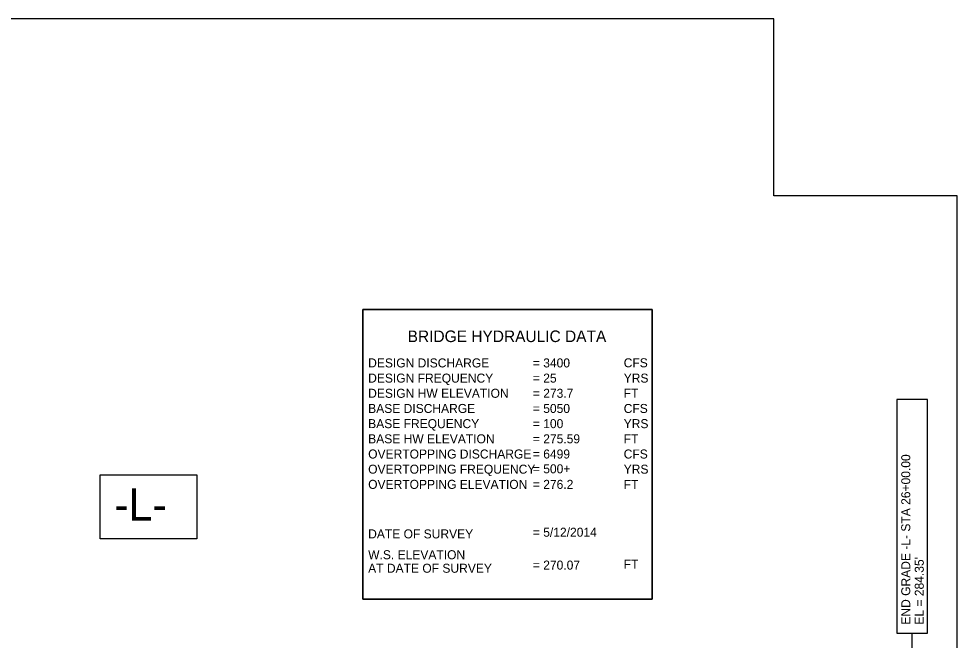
# Model space of a CAD drawing. Extents: x 10000 to 11818, y 10000 to 11025.
# Drawn here: x 10905 to 11635, y 10542 to 11025 of the extents above; entities that cross this region are included whole.
import ezdxf

# ---------------------------------------------------------------- set-up
doc = ezdxf.new("R2010")
doc.units = 0
for name, color, linetype in [('Prop Dimension', 7, 'Continuous'), ('Prop Grid Mask', 7, 'Continuous'), ('Prop VPI Label', 7, 'Continuous'), ('Sheet Layout Profile Border', 7, 'Continuous')]:
    doc.layers.add(name, color=color, linetype=linetype)

msp = doc.modelspace()

# ---------------------------------------------------------------- linework, layer by layer
at = {"layer": 'Prop Dimension'}
msp.add_lwpolyline([(11172.73, 10573.92), (11397.73, 10573.92), (11397.73, 10798.92), (11172.73, 10798.92)], close=True, dxfattribs=at)
at = {"layer": 'Prop Grid Mask'}
for points in [[(11172.73, 10798.92), (11397.73, 10798.92), (11397.73, 10573.92), (11172.73, 10573.92)], [(11588.1, 10547.5), (11611.9, 10547.5), (11611.9, 10729.02), (11588.1, 10729.02)], [(10968.58, 10670.44), (11043.68, 10670.44), (11043.68, 10620.73), (10968.58, 10620.73)]]:
    msp.add_lwpolyline(points, close=True, dxfattribs=at)
at = {"layer": 'Prop VPI Label'}
msp.add_line((11600, 10470.59), (11600, 10547.5), dxfattribs=at)
at = {"layer": 'Sheet Layout Profile Border'}
msp.add_lwpolyline([(10250, 11025), (10250, 10000), (10250, 10000), (11635, 10000), (11635, 10000), (11635, 10887.45), (11635, 10887.45), (11492.45, 10887.45), (11492.45, 11025)], close=True, dxfattribs=at)

# ---------------------------------------------------------------- texts
at = {"layer": 'Prop Dimension'}
for s, height, p in [('BRIDGE HYDRAULIC DATA', 9, (11207.63, 10773.67)), ('DESIGN DISCHARGE', 7, (11176.93, 10753.97)), ('= 3400    ', 7, (11305, 10753.97)), ('CFS', 7, (11375.64, 10754.07)), ('DESIGN FREQUENCY', 7, (11176.93, 10742.17)), ('= 25 ', 7, (11305, 10742.17)), ('YRS', 7, (11375.64, 10742.17)), ('DESIGN HW ELEVATION', 7, (11176.93, 10730.37)), ('= 273.7   ', 7, (11305, 10730.37)), ('FT', 7, (11375.64, 10730.37)), ('BASE DISCHARGE', 7, (11176.93, 10718.57)), ('= 5050    ', 7, (11305, 10718.57)), ('CFS', 7, (11375.64, 10718.57)), ('BASE FREQUENCY', 7, (11176.93, 10706.77)), ('= 100', 7, (11305, 10706.77)), ('YRS', 7, (11375.64, 10706.77)), ('BASE HW ELEVATION', 7, (11176.93, 10694.97)), ('= 275.59  ', 7, (11305, 10694.97)), ('FT', 7, (11375.64, 10694.97)), ('OVERTOPPING DISCHARGE', 7, (11176.93, 10683.17)), ('= 6499    ', 7, (11305, 10683.17)), ('CFS', 7, (11375.64, 10683.17)), ('OVERTOPPING FREQUENCY', 7, (11176.93, 10671.37)), ('= 500+', 7, (11305, 10671.66)), ('YRS', 7, (11375.64, 10671.37)), ('OVERTOPPING ELEVATION', 7, (11176.93, 10659.57)), ('= 276.2   ', 7, (11305, 10659.57)), ('FT', 7, (11375.64, 10659.57)), ('DATE OF SURVEY', 7, (11176.93, 10621.07)), ('= 5/12/2014 ', 7, (11305, 10622.37)), ('W.S. ELEVATION', 7, (11176.93, 10604.87)), ('= 270.07  ', 7, (11305, 10596.82)), ('FT', 7, (11375.64, 10597.42)), ('AT DATE OF SURVEY', 7, (11176.93, 10594.37))]:
    msp.add_text(s, height=height, dxfattribs=at).set_placement(p)
at = {"layer": 'Prop VPI Label'}
for s, p in [('END GRADE -L- STA 26+00.00', (11598.47, 10554.03)), ("EL = 284.35'", (11608.97, 10554.03))]:
    msp.add_text(s, height=7, rotation=90, dxfattribs=at).set_placement(p)
msp.add_text('-L-', height=25, dxfattribs=at).set_placement((10979.52, 10634.95))

doc.saveas('drawing.dxf')
